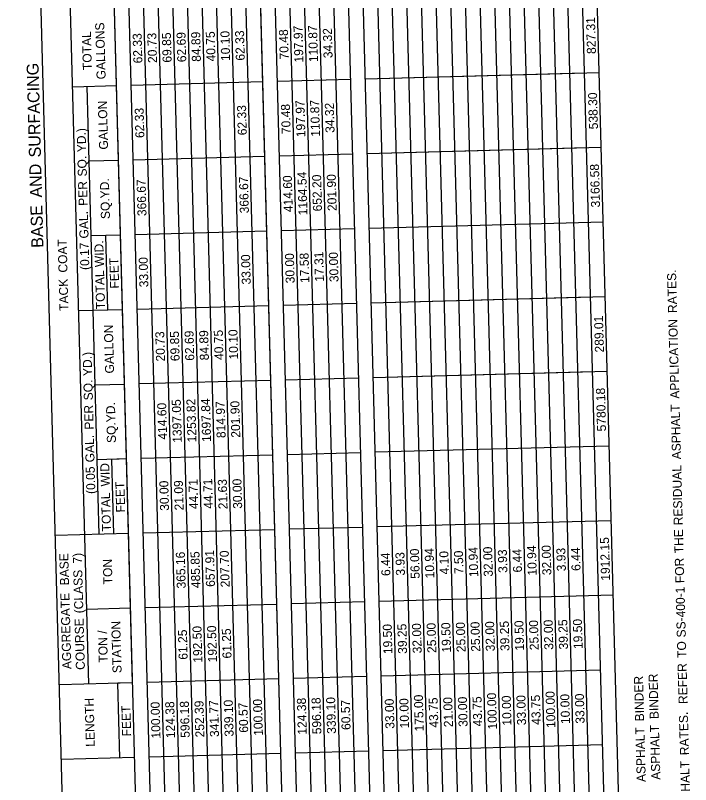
# Model space of a CAD drawing. Extents: x 1930078 to 1931323, y 596452 to 607874.
# Drawn here: x 1930417 to 1930867, y 604226 to 604738 of the extents above; entities that cross this region are included whole.
import ezdxf

# ---------------------------------------------------------------- set-up
doc = ezdxf.new("R2010")
doc.units = 0
doc.layers.add('Default', color=7, linetype='Continuous')

msp = doc.modelspace()

# ---------------------------------------------------------------- linework, layer by layer
at = {"layer": 'Default'}
for p, q in [((1930749.54, 603915.28), (1930709.85, 605393.82)), ((1930759.28, 603915.54), (1930719.59, 605394.08)), ((1930769.03, 603915.8), (1930729.34, 605394.35)), ((1930778.78, 603916.06), (1930739.09, 605394.61)), ((1930788.52, 603916.33), (1930748.83, 605394.87)), ((1930798.27, 603916.59), (1930758.58, 605395.13)), ((1930808.02, 603916.85), (1930768.33, 605395.39)), ((1930817.76, 603917.11), (1930778.07, 605395.65)), ((1930827.51, 603917.37), (1930787.82, 605395.91)), ((1930554.61, 603910.05), (1930514.92, 605388.59)), ((1930564.35, 603910.31), (1930524.66, 605388.85)), ((1930574.1, 603910.57), (1930534.41, 605389.11)), ((1930583.85, 603910.83), (1930544.16, 605389.37)), ((1930593.59, 603911.09), (1930553.9, 605389.64)), ((1930603.34, 603911.35), (1930563.65, 605389.9)), ((1930613.09, 603911.62), (1930573.4, 605390.16)), ((1930622.83, 603911.88), (1930583.14, 605390.42)), ((1930632.58, 603912.14), (1930592.89, 605390.68)), ((1930642.33, 603912.4), (1930602.64, 605390.94)), ((1930652.07, 603912.66), (1930612.38, 605391.21)), ((1930661.82, 603912.92), (1930622.13, 605391.47)), ((1930661.82, 603912.92), (1930622.13, 605391.47)), ((1930671.57, 603913.19), (1930631.88, 605391.73)), ((1930681.31, 603913.45), (1930641.62, 605391.99)), ((1930691.06, 603913.71), (1930651.37, 605392.25)), ((1930700.81, 603913.97), (1930661.12, 605392.51)), ((1930710.55, 603914.23), (1930670.86, 605392.78)), ((1930720.3, 603914.49), (1930680.61, 605393.04)), ((1930730.04, 603914.76), (1930690.35, 605393.3)), ((1930739.79, 603915.02), (1930700.1, 605393.56)), ((1930457.14, 603907.43), (1930417.45, 605385.97)), ((1930466.3, 604292.94), (1930436.95, 605386.5)), ((1930505.88, 603908.74), (1930466.19, 605387.28)), ((1930515.62, 603909), (1930475.93, 605387.54)), ((1930525.37, 603909.26), (1930485.68, 605387.8)), ((1930535.12, 603909.52), (1930495.42, 605388.07)), ((1930544.86, 603909.79), (1930505.17, 605388.33)), ((1930486.2, 604641.67), (1930482.2, 604790.8)), ((1930585, 604594.58), (1930581, 604743.71)), ((1930806.5, 604700.02), (1930650.56, 604695.83)), ((1930796.75, 604699.75), (1930650.56, 604695.83)), ((1930582.33, 604694), (1930494.61, 604691.64)), ((1930582.33, 604694), (1930494.61, 604691.64)), ((1930640.81, 604695.57), (1930592.08, 604694.26)), ((1930640.81, 604695.57), (1930592.08, 604694.26)), ((1930484.87, 604691.38), (1930455.63, 604690.6)), ((1930473.38, 604392.62), (1930465.37, 604690.86)), ((1930642.14, 604645.86), (1930593.41, 604644.55)), ((1930642.14, 604645.86), (1930593.41, 604644.55)), ((1930807.83, 604650.31), (1930651.89, 604646.12)), ((1930798.09, 604650.05), (1930651.89, 604646.12)), ((1930486.2, 604641.67), (1930466.71, 604641.15)), ((1930487.53, 604591.97), (1930486.2, 604641.67)), ((1930583.67, 604644.29), (1930495.95, 604641.94)), ((1930583.67, 604644.29), (1930495.95, 604641.94)), ((1930809.17, 604600.6), (1930653.23, 604596.42)), ((1930809.17, 604600.6), (1930653.23, 604596.42)), ((1930585, 604594.58), (1930497.28, 604592.23)), ((1930585, 604594.58), (1930497.28, 604592.23)), ((1930586.33, 604544.88), (1930585, 604594.58)), ((1930643.48, 604596.15), (1930594.75, 604594.85)), ((1930643.48, 604596.15), (1930594.75, 604594.85)), ((1930487.53, 604591.97), (1930468.04, 604591.44)), ((1930487.53, 604591.97), (1930477.79, 604591.71)), ((1930479.12, 604542), (1930477.79, 604591.71)), ((1930491.54, 604442.85), (1930487.53, 604591.97)), ((1930810.5, 604550.89), (1930654.56, 604546.71)), ((1930800.76, 604550.63), (1930654.56, 604546.71)), ((1930586.33, 604544.88), (1930498.62, 604542.52)), ((1930586.33, 604544.88), (1930498.62, 604542.52)), ((1930589, 604445.46), (1930586.33, 604544.88)), ((1930644.81, 604546.45), (1930596.08, 604545.14)), ((1930644.81, 604546.45), (1930596.08, 604545.14)), ((1930488.87, 604542.26), (1930459.63, 604541.48)), ((1930811.84, 604501.19), (1930655.89, 604497)), ((1930802.09, 604500.93), (1930655.89, 604497)), ((1930490.2, 604492.55), (1930470.71, 604492.03)), ((1930587.67, 604495.17), (1930499.95, 604492.81)), ((1930587.67, 604495.17), (1930499.95, 604492.81)), ((1930646.15, 604496.74), (1930597.42, 604495.43)), ((1930646.15, 604496.74), (1930597.42, 604495.43)), ((1930813.17, 604451.48), (1930657.23, 604447.29)), ((1930813.17, 604451.48), (1930657.23, 604447.29)), ((1930647.48, 604447.03), (1930598.75, 604445.72)), ((1930647.48, 604447.03), (1930598.75, 604445.72)), ((1930491.54, 604442.85), (1930472.04, 604442.32)), ((1930491.54, 604442.85), (1930481.79, 604442.58)), ((1930483.13, 604392.88), (1930481.79, 604442.58)), ((1930495.54, 604293.72), (1930491.54, 604442.85)), ((1930589, 604445.46), (1930501.28, 604443.11)), ((1930589, 604445.46), (1930501.28, 604443.11)), ((1930603.34, 603911.35), (1930589, 604445.46)), ((1930814.51, 604401.77), (1930658.56, 604397.59)), ((1930814.51, 604401.77), (1930658.56, 604397.59)), ((1930590.34, 604395.76), (1930502.62, 604393.4)), ((1930590.34, 604395.76), (1930502.62, 604393.4)), ((1930648.82, 604397.33), (1930600.08, 604396.02)), ((1930648.82, 604397.33), (1930600.08, 604396.02)), ((1930492.87, 604393.14), (1930444.14, 604391.83)), ((1930815.84, 604352.07), (1930659.9, 604347.88)), ((1930815.84, 604352.07), (1930659.9, 604347.88)), ((1930494.21, 604343.43), (1930464.97, 604342.65)), ((1930591.67, 604346.05), (1930503.95, 604343.69)), ((1930591.67, 604346.05), (1930503.95, 604343.69)), ((1930650.15, 604347.62), (1930601.42, 604346.31)), ((1930650.15, 604347.62), (1930601.42, 604346.31)), ((1930651.48, 604297.91), (1930602.75, 604296.6)), ((1930651.48, 604297.91), (1930602.75, 604296.6)), ((1930807.43, 604302.1), (1930661.23, 604298.17)), ((1930807.43, 604302.1), (1930661.23, 604298.17)), ((1930495.54, 604293.72), (1930446.81, 604292.42)), ((1930495.54, 604293.72), (1930485.79, 604293.46)), ((1930487.13, 604243.76), (1930485.79, 604293.46)), ((1930593.01, 604296.34), (1930505.29, 604293.99)), ((1930593.01, 604296.34), (1930505.29, 604293.99)), ((1930808.76, 604252.39), (1930662.57, 604248.47)), ((1930808.76, 604252.39), (1930662.57, 604248.47)), ((1930594.34, 604246.63), (1930506.62, 604244.28)), ((1930594.34, 604246.63), (1930506.62, 604244.28)), ((1930652.82, 604248.2), (1930604.09, 604246.9)), ((1930652.82, 604248.2), (1930604.09, 604246.9)), ((1930610.42, 604011.03), (1930604.09, 604246.9)), ((1930496.88, 604244.02), (1930448.14, 604242.71))]:
    msp.add_line(p, q, dxfattribs=at)

# ---------------------------------------------------------------- texts
for s, height, p in [('GALLONS', 6, (1930477.62, 604695.76)), ('827.31', 6, (1930804.28, 604712.69)), ('10.10', 6, (1930560.57, 604708)), ('62.33', 6, (1930570.32, 604708.25)), ('70.48', 6, (1930599.56, 604709.03)), ('197.97', 6, (1930609.37, 604706.97)), ('110.87', 6, (1930619.11, 604707.23)), ('34.32', 6, (1930628.8, 604709.85)), ('TOTAL', 6, (1930468.45, 604701.96)), ('62.33', 6, (1930502.09, 604706.42)), ('20.73', 6, (1930511.84, 604706.68)), ('69.85', 6, (1930521.59, 604706.92)), ('62.69', 6, (1930531.33, 604707.2)), ('84.89', 6, (1930541.08, 604707.46)), ('40.75', 6, (1930550.83, 604707.7)), (' SURFACING', 8, (1930434.63, 604640.83)), ('538.30', 6, (1930805.63, 604662.51)), ('110.87', 6, (1930620.45, 604657.52)), ('GALLON', 6, (1930479.25, 604648.99)), ('62.33', 6, (1930503.43, 604656.71)), ('62.33', 6, (1930571.65, 604658.54)), ('70.48', 6, (1930600.89, 604659.32)), ('197.97', 6, (1930610.7, 604657.26)), ('34.32', 6, (1930630.13, 604660.14)), (' YD.)', 6, (1930464.73, 604645.02)), (' SQ.', 6, (1930465.16, 604628.83)), (' AND', 8, (1930435.35, 604614.07)), ('3166.58', 6, (1930807.03, 604610.45)), ('366.67', 6, (1930573.05, 604606.51)), ('414.60', 6, (1930602.29, 604607.3)), ('1164.54', 6, (1930612.1, 604605.24)), ('652.20', 6, (1930621.78, 604607.83)), ('201.90', 6, (1930631.53, 604608.09)), (' PER', 6, (1930465.69, 604609.31)), ('SQ.YD.', 6, (1930480.49, 604602.72)), ('366.67', 6, (1930504.83, 604604.67)), ('BASE', 8, (1930436.17, 604583.57)), (' GAL.', 6, (1930466.27, 604587.54)), (' COAT', 6, (1930452.25, 604564.83)), ('(0.17', 6, (1930466.77, 604568.82)), ('TOTAL WID.', 6, (1930477.23, 604542.65)), ('30.00', 6, (1930603.56, 604559.92)), ('17.58', 6, (1930613.31, 604560.17)), ('17.31', 6, (1930623.04, 604561.02)), ('30.00', 6, (1930632.8, 604560.71)), ('FEET', 6, (1930486.61, 604556.44)), ('33.00', 6, (1930506.1, 604557.31)), ('33.00', 6, (1930574.32, 604559.14)), (' RATES.', 6, (1930858.42, 604537.9)), ('TACK', 6, (1930452.87, 604541.57)), ('289.01', 6, (1930809.62, 604513.86)), (' APPLICATION', 6, (1930859.95, 604480.84)), ('GALLON', 6, (1930483.25, 604499.87)), ('69.85', 6, (1930526.92, 604508.09)), ('62.69', 6, (1930536.67, 604508.37)), ('84.89', 6, (1930546.42, 604508.63)), ('40.75', 6, (1930556.16, 604508.87)), ('10.10', 6, (1930565.91, 604509.17)), ('20.73', 6, (1930517.18, 604507.85)), (' YD.)', 6, (1930468.73, 604495.96)), (' SQ.', 6, (1930469.16, 604479.77)), ('5780.18', 6, (1930811.03, 604461.33)), ('1397.05', 6, (1930528.38, 604453.72)), ('1253.82', 6, (1930538.13, 604454.04)), ('1697.84', 6, (1930547.88, 604454.28)), (' PER', 6, (1930469.69, 604460.25)), ('SQ.YD.', 6, (1930484.5, 604453.6)), ('414.60', 6, (1930518.57, 604455.83)), ('814.97', 6, (1930557.56, 604456.86)), ('201.90', 6, (1930567.31, 604457.13)), (' ASPHALT', 6, (1930861.03, 604440.49)), (' GAL.', 6, (1930470.27, 604438.48)), ('(0.05', 6, (1930470.78, 604419.64)), (' WID', 6, (1930480.46, 604422.42)), (' RESIDUAL', 6, (1930862.21, 604396.54)), ('FEET', 6, (1930490.62, 604407.32)), ('30.00', 6, (1930519.85, 604408.45)), ('21.09', 6, (1930529.59, 604408.69)), ('44.71', 6, (1930539.32, 604409.54)), ('44.71', 6, (1930549.07, 604409.8)), ('21.63', 6, (1930558.83, 604409.48)), ('30.00', 6, (1930568.58, 604409.76)), ('TOTAL', 6, (1930481.2, 604394.74)), (' THE', 6, (1930862.71, 604377.9)), ('1912.15', 6, (1930813.7, 604361.86)), ('10.94', 6, (1930764.84, 604365.28)), ('32.00', 6, (1930774.59, 604365.54)), (' BASE', 6, (1930453.34, 604356.55)), (' 7)', 6, (1930461.95, 604371.03)), ('365.16', 6, (1930530.99, 604356.66)), ('485.85', 6, (1930540.74, 604356.9)), ('657.91', 6, (1930550.47, 604357.77)), ('207.70', 6, (1930560.23, 604357.46)), ('6.44', 6, (1930667.32, 604365)), ('3.93', 6, (1930677.06, 604365.25)), ('56.00', 6, (1930686.87, 604363.19)), ('10.94', 6, (1930696.62, 604363.45)), ('4.10', 6, (1930706.3, 604366.04)), ('7.50', 6, (1930716.05, 604366.3)), ('10.94', 6, (1930725.86, 604364.24)), ('32.00', 6, (1930735.6, 604364.5)), ('3.93', 6, (1930745.29, 604367.08)), ('6.44', 6, (1930755.03, 604367.35)), ('3.93', 6, (1930784.27, 604368.12)), ('6.44', 6, (1930794.02, 604368.4)), ('TON', 6, (1930482.15, 604359.46)), (' FOR', 6, (1930863.25, 604358)), (' (CLASS', 6, (1930462.84, 604337.92)), (' SS-400-1', 6, (1930864.22, 604321.82)), ('AGGREGATE', 6, (1930454.78, 604302.95)), ('COURSE', 6, (1930463.79, 604302.48)), ('STATION', 6, (1930488.24, 604300.33)), ('32.00', 6, (1930688.21, 604313.48)), ('25.00', 6, (1930697.95, 604313.74)), ('19.50', 6, (1930707.7, 604314.01)), ('25.00', 6, (1930717.44, 604314.27)), ('25.00', 6, (1930727.19, 604314.53)), ('32.00', 6, (1930736.94, 604314.79)), ('39.25', 6, (1930746.69, 604315.02)), ('19.50', 6, (1930756.43, 604315.31)), ('25.00', 6, (1930766.18, 604315.57)), ('32.00', 6, (1930775.92, 604315.84)), ('39.25', 6, (1930785.67, 604316.06)), ('19.50', 6, (1930795.42, 604316.36)), (' /', 6, (1930478.59, 604324.32)), ('61.25', 6, (1930532.26, 604309.26)), ('192.50', 6, (1930542.07, 604307.23)), ('192.50', 6, (1930551.82, 604307.49)), ('61.25', 6, (1930561.5, 604310.05)), ('19.50', 6, (1930668.71, 604312.96)), ('39.25', 6, (1930678.46, 604313.19)), ('TON', 6, (1930479.05, 604307.3)), (' TO', 6, (1930864.58, 604308.23)), ('  REFER', 6, (1930865.47, 604275.28)), (' BINDER', 6, (1930836.46, 604265.97)), (' BINDER', 6, (1930846.17, 604267.49)), ('100.00', 6, (1930777.32, 604263.8)), ('LENGTH', 6, (1930470.42, 604251.26)), ('339.10', 6, (1930562.9, 604258.04)), ('100.00', 6, (1930582.39, 604258.57)), ('124.38', 6, (1930611.63, 604259.34)), ('596.18', 6, (1930621.38, 604259.6)), ('339.10', 6, (1930631.12, 604259.88)), ('60.57', 6, (1930640.81, 604262.46)), ('33.00', 6, (1930670.05, 604263.25)), ('10.00', 6, (1930679.79, 604263.51)), ('175.00', 6, (1930689.6, 604261.45)), ('43.75', 6, (1930699.29, 604264)), ('21.00', 6, (1930709.03, 604264.3)), ('30.00', 6, (1930718.78, 604264.56)), ('43.75', 6, (1930728.53, 604264.79)), ('100.00', 6, (1930738.33, 604262.75)), ('10.00', 6, (1930748.02, 604265.34)), ('33.00', 6, (1930757.76, 604265.61)), ('43.75', 6, (1930767.51, 604265.83)), ('10.00', 6, (1930787, 604266.39)), ('33.00', 6, (1930796.75, 604266.65)), ('FEET', 6, (1930494.62, 604258.2)), ('100.00', 6, (1930514.17, 604256.74)), ('124.38', 6, (1930523.91, 604256.98)), ('596.18', 6, (1930533.66, 604257.24)), ('252.39', 6, (1930543.41, 604257.5)), ('341.77', 6, (1930553.15, 604257.77)), ('60.57', 6, (1930572.58, 604260.62)), (' RATES.', 6, (1930866.32, 604243.41)), ('  ASPHALT', 6, (1930837.6, 604223.29)), ('  ASPHALT', 6, (1930847.32, 604224.81)), (' ASPHALT', 6, (1930867.41, 604203.06))]:
    msp.add_text(s, height=height, rotation=91.5377, dxfattribs=at).set_placement(p)

doc.saveas('drawing.dxf')
